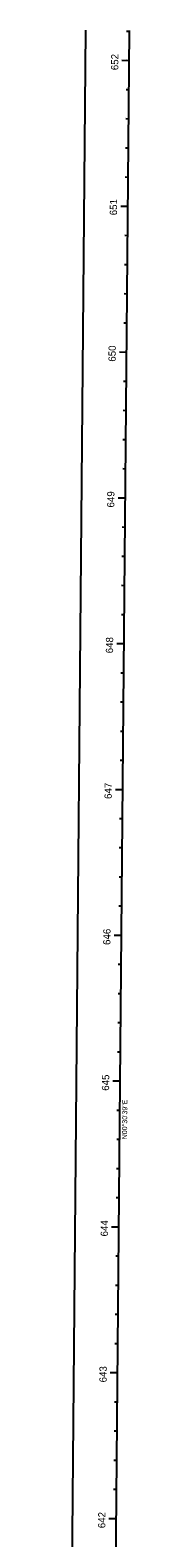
# Model space of a CAD drawing. Extents: x 2003883 to 2007688, y 399149 to 412300.
# Drawn here: x 2003910 to 2003953, y 411266 to 412300 of the extents above; entities that cross this region are included whole.
import ezdxf

# ---------------------------------------------------------------- set-up
doc = ezdxf.new("R2010")
doc.units = 0
for name, color, linetype in [('BaselineSurvey', 7, 'Continuous'), ('BaselineTextWt0', 7, 'Continuous'), ('BaselineTextWt2', 7, 'Continuous'), ('DataBoxWt2', 7, 'Continuous'), ('Default', 7, 'Continuous'), ('EaseLine_ep', 7, 'Continuous'), ('PropertyLine_ep', 7, 'Continuous'), ('PropertyLineHook_ep', 7, 'Continuous'), ('PropertyLineSymbol_ep', 7, 'Continuous'), ('SubDivLineText', 7, 'Continuous'), ('SubLotNumberText', 7, 'Continuous'), ('SubVacOrigLotStaTie', 7, 'Continuous')]:
    doc.layers.add(name, color=color, linetype=linetype)

msp = doc.modelspace()

# ---------------------------------------------------------------- linework, layer by layer
at = {"layer": 'DataBoxWt2'}
for p, q in [((2003952.8, 412278.9), (2003950.8, 412279)), ((2003951.1, 412078.9), (2003946.1, 412079)), ((2003949.3, 411879), (2003947.3, 411879)), ((2003947.5, 411679), (2003945.5, 411679)), ((2003945.7, 411479), (2003943.7, 411479)), ((2003943.9, 411279), (2003941.9, 411279))]:
    msp.add_line(p, q, dxfattribs=at)
at = {"layer": 'Default'}
msp.add_line((2003939.7, 410808.6), (2003953, 412299.6), dxfattribs=at)
at = {"layer": 'EaseLine_ep'}
msp.add_line((2003909.7, 410808.9), (2003923, 412299.9), dxfattribs=at)
at = {"layer": 'PropertyLine_ep'}
msp.add_line((2003939.7, 410808.6), (2003953, 412299.6), dxfattribs=at)
at = {"layer": 'PropertyLineHook_ep'}
for p, q in [((2003953, 412298.9), (2003951, 412299)), ((2003952.8, 412278.9), (2003947.8, 412279)), ((2003952.7, 412258.9), (2003950.7, 412259)), ((2003952.5, 412238.9), (2003950.5, 412239)), ((2003952.3, 412218.9), (2003950.3, 412219)), ((2003952.1, 412198.9), (2003950.1, 412199)), ((2003952, 412178.9), (2003947, 412179)), ((2003951.8, 412158.9), (2003949.8, 412159)), ((2003951.6, 412138.9), (2003949.6, 412139)), ((2003951.4, 412118.9), (2003949.4, 412119)), ((2003951.2, 412098.9), (2003949.2, 412099)), ((2003951.1, 412078.9), (2003946.1, 412079)), ((2003950.9, 412058.9), (2003948.9, 412059)), ((2003950.7, 412038.9), (2003948.7, 412039)), ((2003950.5, 412018.9), (2003948.5, 412019)), ((2003950.4, 411998.9), (2003948.4, 411999)), ((2003950.2, 411978.9), (2003945.2, 411979)), ((2003950, 411958.9), (2003948, 411959)), ((2003949.8, 411938.9), (2003947.8, 411939)), ((2003949.6, 411918.9), (2003947.6, 411919)), ((2003949.5, 411898.9), (2003947.5, 411899)), ((2003949.3, 411879), (2003944.3, 411879)), ((2003949.1, 411859), (2003947.1, 411859)), ((2003948.9, 411839), (2003946.9, 411839)), ((2003948.7, 411819), (2003946.7, 411819)), ((2003948.6, 411799), (2003946.6, 411799)), ((2003948.4, 411779), (2003943.4, 411779)), ((2003948.2, 411759), (2003946.2, 411759)), ((2003948, 411739), (2003946, 411739)), ((2003947.9, 411719), (2003945.9, 411719)), ((2003947.7, 411699), (2003945.7, 411699)), ((2003947.5, 411679), (2003942.5, 411679)), ((2003947.3, 411659), (2003945.3, 411659)), ((2003947.1, 411639), (2003945.1, 411639)), ((2003947, 411619), (2003945, 411619)), ((2003946.8, 411599), (2003944.8, 411599)), ((2003946.6, 411579), (2003941.6, 411579)), ((2003946.4, 411559), (2003944.4, 411559)), ((2003946.2, 411539), (2003944.2, 411539)), ((2003946.1, 411519), (2003944.1, 411519)), ((2003945.9, 411499), (2003943.9, 411499)), ((2003945.7, 411479), (2003940.7, 411479)), ((2003945.5, 411459), (2003943.5, 411459)), ((2003945.4, 411439), (2003943.4, 411439)), ((2003945.2, 411419), (2003943.2, 411419)), ((2003945, 411399), (2003943, 411399)), ((2003944.8, 411379), (2003939.8, 411379)), ((2003944.6, 411359), (2003942.6, 411359)), ((2003944.5, 411339), (2003942.5, 411339)), ((2003944.3, 411319), (2003942.3, 411319)), ((2003944.1, 411299), (2003942.1, 411299)), ((2003943.9, 411279), (2003938.9, 411279))]:
    msp.add_line(p, q, dxfattribs=at)
at = {"layer": 'SubDivLineText'}
for p, q in [((2003952.8, 412278.9), (2003950.8, 412279)), ((2003952, 412178.9), (2003950, 412179)), ((2003951.1, 412078.9), (2003946.1, 412079)), ((2003950.2, 411978.9), (2003948.2, 411979)), ((2003949.3, 411879), (2003947.3, 411879)), ((2003948.4, 411779), (2003946.4, 411779)), ((2003947.5, 411679), (2003945.5, 411679)), ((2003946.6, 411579), (2003941.6, 411579)), ((2003945.7, 411479), (2003943.7, 411479)), ((2003944.8, 411379), (2003942.8, 411379)), ((2003943.9, 411279), (2003941.9, 411279))]:
    msp.add_line(p, q, dxfattribs=at)
at = {"layer": 'SubVacOrigLotStaTie'}
msp.add_line((2003951.1, 412078.9), (2003946.1, 412079), dxfattribs=at)

# ---------------------------------------------------------------- texts
at = {"layer": 'BaselineSurvey'}
msp.add_text('650', height=4.98, rotation=89.489, dxfattribs=at).set_placement((2003943.5, 412072.5))
at = {"layer": 'BaselineTextWt0'}
msp.add_text('N00°30\'39"E', height=3.48, rotation=89.489, dxfattribs=at).set_placement((2003951.3, 411539.2))
at = {"layer": 'BaselineTextWt2'}
msp.add_text('650', height=4.98, rotation=89.489, dxfattribs=at).set_placement((2003943.5, 412072.5))
at = {"layer": 'PropertyLineSymbol_ep'}
for s, p in [('652', (2003945.3, 412272.4)), ('651', (2003944.4, 412172.9)), ('650', (2003943.5, 412072.5)), ('649', (2003942.6, 411972.5)), ('648', (2003941.7, 411872.5)), ('647', (2003940.8, 411772.6)), ('646', (2003939.9, 411672.5)), ('645', (2003939, 411572.5)), ('644', (2003938.2, 411472.6)), ('643', (2003937.3, 411372.5)), ('642', (2003936.4, 411272.5))]:
    msp.add_text(s, height=4.98, rotation=89.489, dxfattribs=at).set_placement(p)
at = {"layer": 'SubLotNumberText'}
for s, p in [('650', (2003943.5, 412072.5)), ('645', (2003939, 411572.5))]:
    msp.add_text(s, height=4.98, rotation=89.489, dxfattribs=at).set_placement(p)

doc.saveas('drawing.dxf')
